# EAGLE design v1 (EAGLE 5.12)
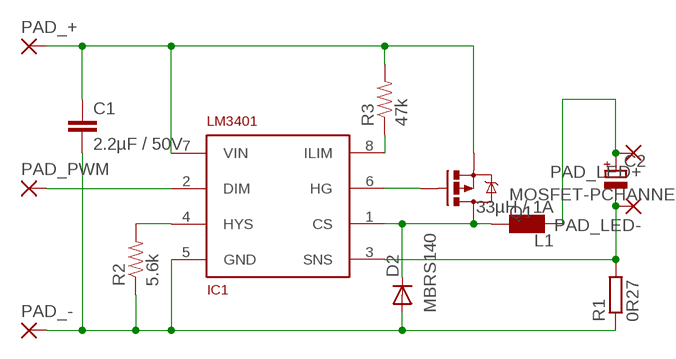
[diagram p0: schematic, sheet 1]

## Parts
C1  2.2µF / 50V  C-EUC1210  [C1210]
C2  CPOL-EUSMCA  [SMC_A]
D2  MBRS140  DIODE-SMB  [SMB]
IC1  LM3401  [MSOP8]
L1  33µH / 1A  L_PIS2816  [PIS2816]
PAD_+  SMD2  [SMD1,27-2,54]
PAD_-  SMD2  [SMD1,27-2,54]
PAD_LED+  SMD2  [SMD1,27-2,54]
PAD_LED-  SMD2  [SMD1,27-2,54]
PAD_PWM  SMD2  [SMD1,27-2,54]
Q1  MOSFET-PCHANNEL  [SOT23]
R1  0R27  R-EU_R1206  [R1206]
R2  5.6k  RESISTOR0805-RES  [0805]
R3  47k  RESISTOR0805-RES  [0805]

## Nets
GND: C1.2 D2.A IC1.5(GND) PAD_-.1(P) R1.1 R2.1
N$1: C2.- IC1.3(SNS) PAD_LED-.1(P) R1.2
N$2: C2.+ L1.P$2 PAD_LED+.1(P)
N$3: D2.C IC1.1(CS) L1.P$1 Q1.3(D)
N$5: IC1.4(HYS) R2.2
N$7: IC1.8(ILIM) R3.1
N$8: C1.1 IC1.7(VIN) PAD_+.1(P) Q1.2(S) R3.2
N$9: IC1.2(DIM) PAD_PWM.1(P)
N$10: IC1.6(HG) Q1.1(G)

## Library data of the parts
C1 = rcl:C-EU: CAPACITOR, European symbol
C2 = rcl:CPOL-EU: POLARIZED CAPACITOR, European symbol
D2 = diode:DIODE-: DIODE
IC1 = seb:LM3401
L1 = seb:L_PIS2816
PAD_+ PAD_- PAD_LED+ PAD_LED- PAD_PWM = wirepad:SMD2: SMD PAD
Q1 = SparkFun:MOSFET-PCHANNEL
R1 = rcl:R-EU_: RESISTOR, European symbol
R2 R3 = SparkFun:RESISTOR: Resistor

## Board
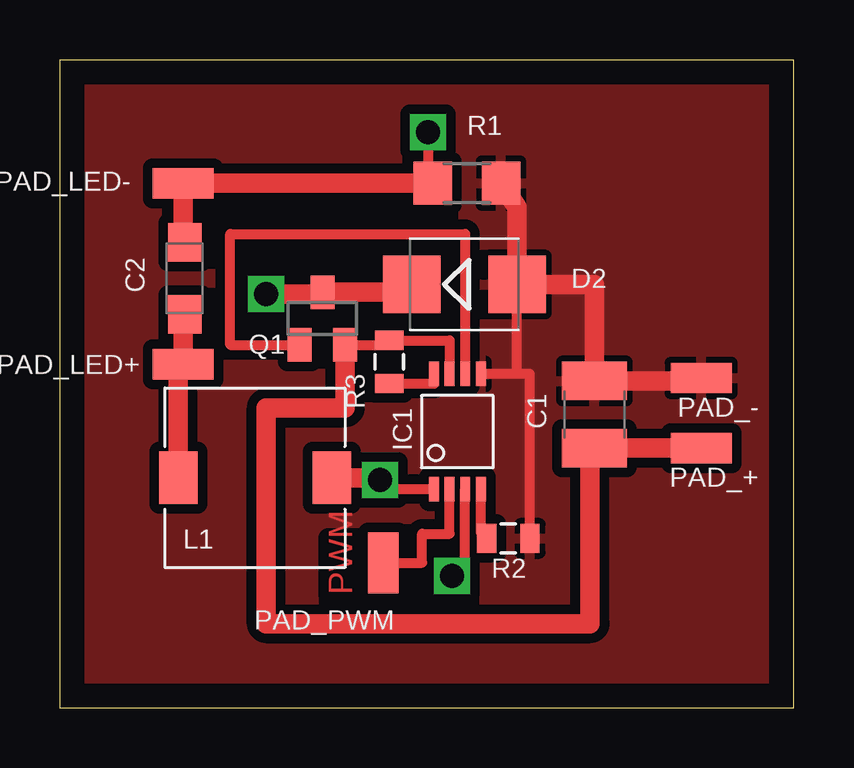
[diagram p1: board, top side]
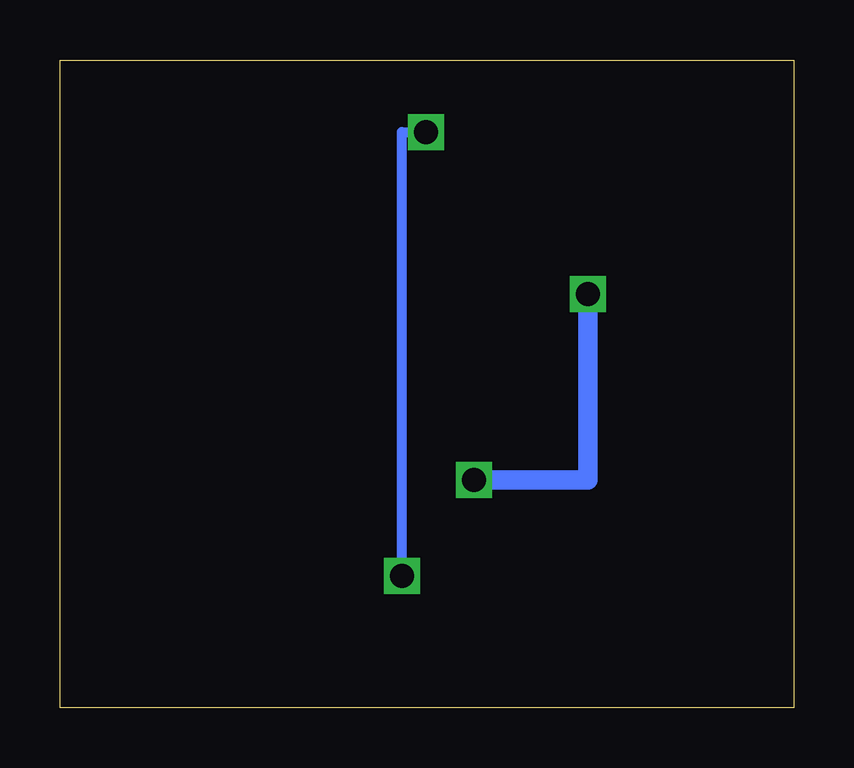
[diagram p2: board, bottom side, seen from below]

Size 30.6 x 27 mm. Coordinates in mm from the lower left corner, seen from the top.
Outline: 0,0 30.6,0 30.6,27 0,27 0,0
Copper layers (1*16): Top 0.035mm / dielectric 1.5mm / Bottom 0.035mm
Design rules "default": minimum track width 10mil, minimum drill 24mil, track to track 8mil, track to pad 8mil, pad to pad 8mil, via to via 8mil, smd to smd 8mil, copper to edge 40mil, drill to drill 8mil, minimum pad ring 10mil, minimum via ring 8mil, stop-mask expansion 4mil, vias tented up to drill 0mil, thermal gap 10mil

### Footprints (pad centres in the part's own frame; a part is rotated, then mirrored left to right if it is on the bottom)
C1210 = smd 1.6 x 2.7: 1 -1.4,0; 2 1.4,0
SMC_A = smd 1.6 x 1.4: + -1.5,0; - 1.5,0
SMB = smd 2.4 x 2.4: A 2.2,0; C -2.2,0
MSOP8 = smd 0.41 x 1.02: 1 -0.975,-2.4; 2 -0.325,-2.4; 3 0.325,-2.4; 4 0.975,-2.4; 5 0.975,2.4; 6 0.325,2.4; 7 -0.325,2.4; 8 -0.975,2.4
PIS2816 = smd 2.2 x 1.6: P$1 0,3.2; P$2 0,-3.2
SMD1,27-2,54 = smd 1.27 x 2.54: 1 0,0
SOT23 = smd 1 x 1.4: 1 -0.95,-1.1; 2 0.95,-1.1; 3 0,1.1
R1206 = smd 1.6 x 1.803: 1 -1.422,0; 2 1.422,0
0805 = smd 0.8 x 1.2: 1 -0.9,0; 2 0.9,0

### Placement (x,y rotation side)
C1  22.28,12.22 90 top
C2  5.2,17.9 90 top
D2  16.86,17.64 0 top
IC1  16.57,11.51 0 top
L1  8.13,9.58 270 top
PAD_+  26.73,10.82 90 top
PAD_-  26.73,13.74 90 top
PAD_LED+  5.14,14.32 90 top
PAD_LED-  5.14,21.86 90 top
PAD_PWM  13.47,6.04 0 top
Q1  10.94,16.22 0 top
R1  16.97,21.86 180 top
R2  18.69,7.05 180 top
R3  13.73,14.41 90 top

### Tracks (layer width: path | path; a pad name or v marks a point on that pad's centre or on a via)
GND
  Top 0.406: C1.2 22.28,13.5 | R2.1 19.59,13.91 19.06,13.91 | 19.06,13.91 D2.A | 19.06,13.91 IC1.5
  Top 0.813: R1.1 19.06,20.86 D2.A 22.28,17.64 C1.2 26.73,13.62 PAD_-.1
  pour Top (isolate 0.406): 0,0 30.6,0 30.6,27 0,27
N$1  (via drill 1)
  Top 0.406: IC1.3 16.89,5.5 v16.35,5.5 | v15.35,24 15.35,21.86
  Top 0.813: R1.2 15.35,21.86 PAD_LED-.1 5.14,20.15 C2.-
  Bottom 0.406: v16.35,5.5 16.35,24 v15.35,24
N$2
  Top 0.813: L1.P$2 4.93,14.32 PAD_LED+.1 5.14,15.9 C2.+
N$3  (via drill 1)
  Top 0.406: IC1.1 13.35,9.11 v13.35,9.5
  Top 0.813: D2.C 14.66,17.32 Q1.3 10.94,17.25 v8.6,17.25 | L1.P$1 13.35,9.58 v13.35,9.5
  Bottom 0.813: v13.35,9.5 8.6,9.5 v8.6,17.25
N$4
  pour Top: 1,11.7 3.2,11.7 3.2,25 1,25
  pour Top: 29.3,14.6 29.3,16.8 24.9,16.9 24.9,14.7
  pour Top: 29.3,7.4 29.3,9.6 24.3,9.6 24.3,7.4
N$5
  Top 0.406: IC1.4 17.55,7.31 R2.2
N$7
  Top 0.406: R3.1 15.59,13.51 IC1.8
N$8
  Top 0.406: IC1.7 16.25,15.31 R3.2 13.73,15.12 Q1.2
  Top 0.813: PAD_+.1 C1.1 22.1,10.82 22.1,3.5 8.6,3.5 8.6,12.5 11.89,12.5 Q1.2
N$9
  Top 0.406: IC1.2 16.25,7.25 15.1,7.25 15.1,6.04 PAD_PWM.1
N$10
  Top 0.406: Q1.1 7.1,15.12 7.1,19.75 16.89,19.75 IC1.6

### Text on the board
Top: PWM
tRestrict: LED- | GND | LED+ | +12V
